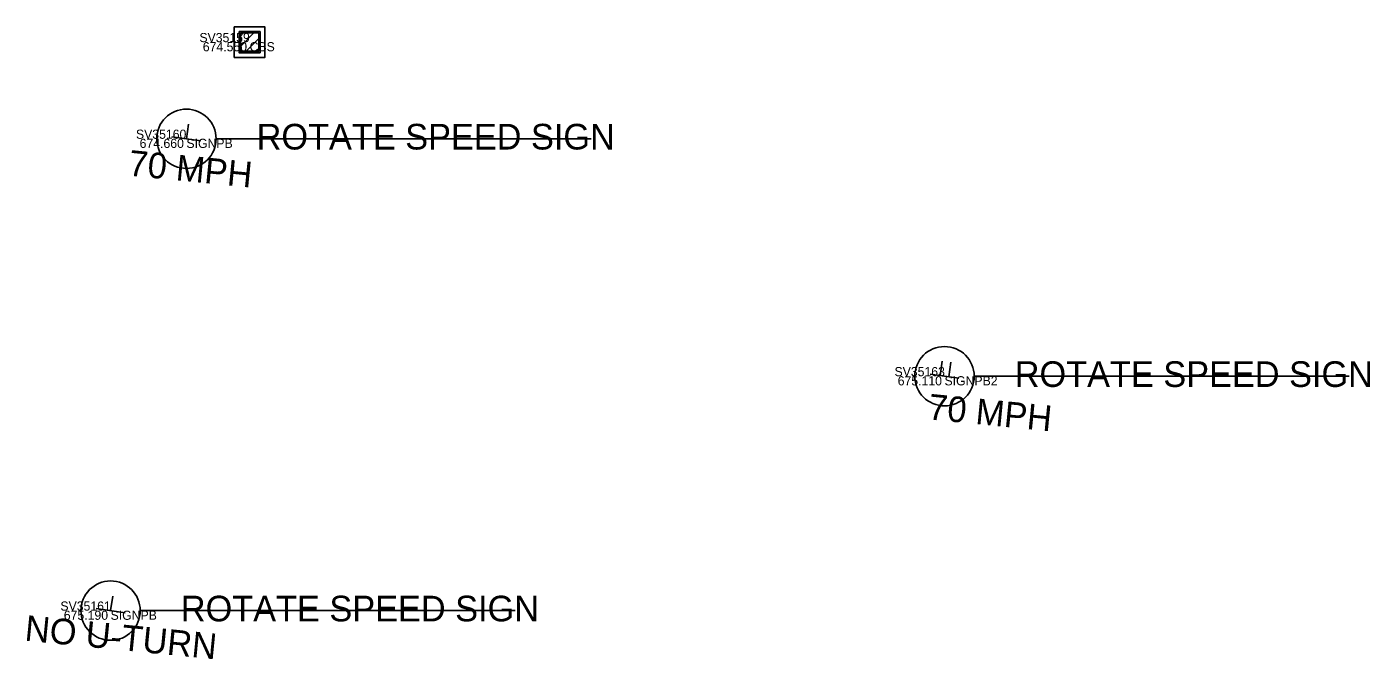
# Model space of a CAD drawing. Extents: x 1660019 to 1662995, y 619975 to 620342.
# Drawn here: x 1661297.3 to 1661444, y 619974.5 to 620043.6 of the extents above; entities that cross this region are included whole.
import ezdxf

# ---------------------------------------------------------------- set-up
doc = ezdxf.new("R2010")
doc.units = 0
for name, color, linetype in [('BR_X_Rail_Object', 7, 'Continuous'), ('DR_X_Cells', 7, 'Continuous'), ('GK_Drainage_Nodes', 7, 'Continuous'), ('RD_X_GR_Bar', 7, 'Continuous'), ('RD_X_Text', 7, 'Continuous'), ('RD_X_Wall', 7, 'Continuous'), ('SC_Scratch6', 7, 'Continuous'), ('SN_X_Public', 7, 'Continuous')]:
    doc.layers.add(name, color=color, linetype=linetype)

msp = doc.modelspace()

# ---------------------------------------------------------------- linework, layer by layer
at = {"layer": 'DR_X_Cells'}
for p, q in [((1661320.48, 620041.29), (1661322.24, 620043.05)), ((1661320.48, 620042.42), (1661321.11, 620043.05)), ((1661321.08, 620040.75), (1661322.78, 620042.45)), ((1661322.21, 620040.75), (1661322.78, 620041.32))]:
    msp.add_line(p, q, dxfattribs=at)
for points in [[(1661319.96, 620043.57), (1661323.3, 620043.57), (1661323.3, 620040.23), (1661319.96, 620040.23)], [(1661320.48, 620043.05), (1661322.78, 620043.05), (1661322.78, 620040.75), (1661320.48, 620040.75)], [(1661320.63, 620042.9), (1661322.63, 620042.9), (1661322.63, 620040.9), (1661320.63, 620040.9)]]:
    msp.add_lwpolyline(points, close=True, dxfattribs=at)
at = {"layer": 'GK_Drainage_Nodes'}
for p, q in [((1661321.63, 620043.57), (1661321.63, 620043.57)), ((1661320.63, 620041.9), (1661320.63, 620041.9)), ((1661321.63, 620042.9), (1661321.63, 620042.9)), ((1661321.63, 620041.9), (1661321.63, 620041.9)), ((1661321.63, 620041.9), (1661321.63, 620041.9)), ((1661321.63, 620041.9), (1661321.63, 620041.9)), ((1661322.63, 620041.9), (1661322.63, 620041.9)), ((1661321.63, 620040.9), (1661321.63, 620040.9)), ((1661321.63, 620040.23), (1661321.63, 620040.23))]:
    msp.add_line(p, q, dxfattribs=at)
at = {"layer": 'SC_Scratch6'}
for p, q in [((1661317.97, 620031.35), (1661358.93, 620031.35)), ((1661400.76, 620005.43), (1661441.72, 620005.43)), ((1661309.69, 619979.84), (1661350.65, 619979.84))]:
    msp.add_line(p, q, dxfattribs=at)
for centre in [(1661314.73, 620031.35), (1661397.52, 620005.43), (1661306.45, 619979.84)]:
    msp.add_circle(centre, 3.24, dxfattribs=at)
at = {"layer": 'SN_X_Public'}
for p, q in [((1661316.31, 620031.13), (1661313.15, 620031.57)), ((1661314.73, 620031.35), (1661314.95, 620032.93)), ((1661314.73, 620031.35), (1661314.73, 620031.35)), ((1661397.04, 620005.5), (1661397.26, 620007.08)), ((1661398, 620005.36), (1661398.22, 620006.95)), ((1661399.1, 620005.21), (1661395.94, 620005.65)), ((1661397.52, 620005.43), (1661397.52, 620005.43)), ((1661306.45, 619979.84), (1661306.69, 619981.42)), ((1661308.03, 619979.6), (1661304.87, 619980.08)), ((1661306.45, 619979.84), (1661306.45, 619979.84))]:
    msp.add_line(p, q, dxfattribs=at)

# ---------------------------------------------------------------- texts
at = {"layer": 'BR_X_Rail_Object'}
for s, p in [('CBS', (1661321.63, 620040.9)), ('SIGNPB', (1661314.73, 620030.35)), ('SIGNPB2', (1661397.52, 620004.43)), ('SIGNPB', (1661306.45, 619978.84))]:
    msp.add_text(s, height=1, dxfattribs=at).set_placement(p)
at = {"layer": 'RD_X_GR_Bar'}
for s, p in [('674.550', (1661316.52, 620040.9)), ('674.660', (1661309.62, 620030.35)), ('675.110', (1661392.41, 620004.43)), ('675.190', (1661301.34, 619978.84))]:
    msp.add_text(s, height=1, dxfattribs=at).set_placement(p)
at = {"layer": 'RD_X_Text'}
for s, p in [('70 MPH', (1661308.32, 620027.34)), ('70 MPH', (1661395.65, 620000.73)), ('NO U-TURN', (1661297, 619976.57))]:
    msp.add_text(s, height=2.8, rotation=354.3921, dxfattribs=at).set_placement(p)
at = {"layer": 'RD_X_Wall'}
for s, p in [('SV35159', (1661316.15, 620041.9)), ('SV35160', (1661309.22, 620031.35)), ('SV35163', (1661392.06, 620005.43)), ('SV35161', (1661300.97, 619979.84))]:
    msp.add_text(s, height=1, dxfattribs=at).set_placement(p)
at = {"layer": 'SC_Scratch6'}
for p in [(1661322.4, 620030.18), (1661405.19, 620004.26), (1661314.12, 619978.67)]:
    msp.add_text('ROTATE SPEED SIGN', height=2.8, dxfattribs=at).set_placement(p)

doc.saveas('drawing.dxf')
